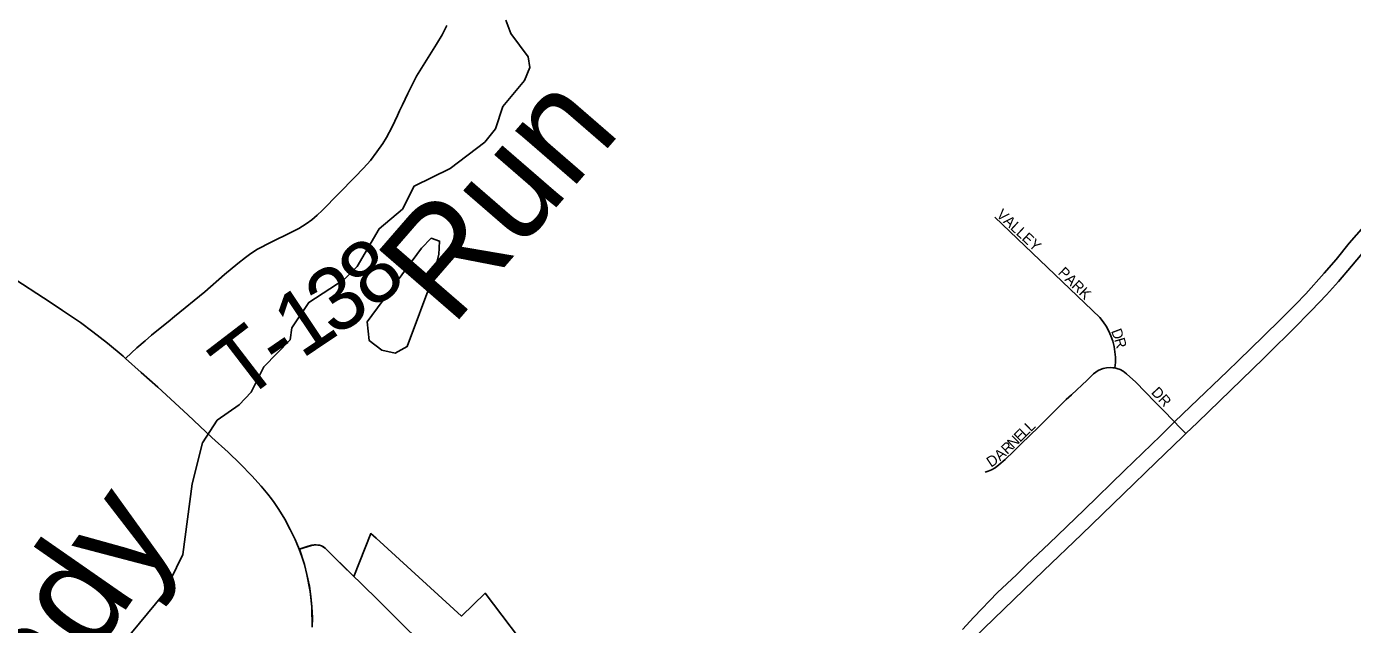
# Model space of a CAD drawing. Extents: x 1410790 to 1770854, y 448063 to 770588.
# Drawn here: x 1542170 to 1548426, y 591709 to 594533 of the extents above; entities that cross this region are included whole.
import ezdxf

# ---------------------------------------------------------------- set-up
doc = ezdxf.new("R2010")
doc.units = 0
for name, color, linetype in [('GM_X_City_Street', 7, 'Continuous'), ('GM_X_Corporation', 7, 'Continuous'), ('GM_X_County_Road', 7, 'Continuous'), ('GM_X_Minor_Lake', 7, 'Continuous'), ('GM_X_Minor_River', 7, 'Continuous'), ('GM_X_Minor_River_Text', 7, 'Continuous'), ('GM_X_State_Route', 7, 'Continuous'), ('GM_X_Township_Road', 7, 'Continuous'), ('GM_X_Township_Road_Text', 7, 'Continuous'), ('GM_X_Township_Subdivision', 7, 'Continuous'), ('GM_X_Township_Subdivision_Text', 7, 'Continuous'), ('GM_X_US_Route', 7, 'Continuous')]:
    doc.layers.add(name, color=color, linetype=linetype)

msp = doc.modelspace()

# ---------------------------------------------------------------- linework, layer by layer
at = {"layer": 'GM_X_City_Street'}
for points in [[(1543742.3, 591908.6), (1543714.4, 591935.8)], [(1544024.3, 591630.1), (1544005.1, 591648.5), (1543957.6, 591695.5), (1543920.8, 591732.4), (1543839.8, 591813.5), (1543742.3, 591908.6)]]:
    msp.add_lwpolyline(points, dxfattribs=at)
at = {"layer": 'GM_X_Corporation'}
msp.add_lwpolyline([(1543518.3, 591696.1), (1543516.7, 591791.8), (1543508.4, 591865.5), (1543493.4, 591944.9), (1543481.4, 591992.8), (1543457.5, 592064.9), (1543515.3, 592082.5), (1543536.5, 592084.9), (1543549.2, 592083.6), (1543561.8, 592080.3), (1543579.7, 592068.8), (1543714.4, 591935.8), (1543794.2, 592138.6), (1543820.6, 592116.3), (1544221.9, 591748.9), (1544334.9, 591856.5), (1544575.1, 591538.1)], dxfattribs=at)
at = {"layer": 'GM_X_County_Road'}
msp.add_lwpolyline([(1543457.4, 592064.9), (1543499.5, 592078.2), (1543516.6, 592082.9), (1543527.6, 592084.6), (1543536.5, 592084.9), (1543544.9, 592084.3), (1543553.3, 592082.9), (1543561.7, 592080.3), (1543570.7, 592075.4), (1543579.8, 592068.8), (1543654.1, 591994), (1543714.4, 591935.8)], dxfattribs=at)
at = {"layer": 'GM_X_Minor_Lake'}
for points in [[(1543776.8, 593138), (1543787.1, 593049.5), (1543846.3, 593004.1), (1543910.2, 592990.7), (1543966.9, 593021.6), (1544087.4, 593346), (1544115.6, 593455.7), (1544118.9, 593519.9), (1544079.1, 593532.7), (1544034.1, 593485.6)], [(1544034.1, 593485.6), (1543776.8, 593138)]]:
    msp.add_lwpolyline(points, dxfattribs=at)
at = {"layer": 'GM_X_Minor_River'}
msp.add_lwpolyline([(1542438.4, 591395.3), (1542816, 591852.6), (1542907.8, 592039.2), (1542952.4, 592373.3), (1543000.3, 592566.8), (1543070.5, 592673.7), (1543174.1, 592745.7), (1543229.4, 592806.7), (1543289.8, 592925.8), (1543414.5, 593053.5), (1543421.6, 593109.5), (1543502.1, 593230.2), (1543668.5, 593338.9), (1543729.8, 593399.8), (1543833.5, 593578.1), (1543943.5, 593670.1), (1543999.7, 593779.2), (1544169.6, 593861.8), (1544332.4, 593986.7), (1544383.7, 594049.8), (1544417.8, 594155.4), (1544520.4, 594277.6), (1544545.6, 594339.2), (1544536.6, 594389.6), (1544454.6, 594499.7), (1544431.8, 594562.3)], dxfattribs=at)
at = {"layer": 'GM_X_State_Route'}
for points in [[(1542088.3, 593357.8), (1542282, 593230.8)], [(1542282, 593230.8), (1542340.7, 593192.3), (1542424.5, 593134.6), (1542482.7, 593091.7), (1542552.3, 593036.9), (1542625.6, 592976.1), (1542637.1, 592965.7), (1542710.9, 592899.5), (1542789.2, 592829.7), (1542931.6, 592698.4), (1543043.8, 592592.7), (1543121.5, 592522), (1543178.2, 592467.3), (1543233.3, 592410.8), (1543278, 592362.5), (1543309.5, 592324.4), (1543326, 592302.7), (1543339.4, 592285), (1543361.4, 592252), (1543388.3, 592206.6), (1543414.8, 592157.3), (1543437.6, 592109.8), (1543445.9, 592091), (1543457.4, 592064.9), (1543469.6, 592030.7), (1543481.4, 591992.8), (1543493.4, 591944.8), (1543504.7, 591890), (1543512.1, 591841), (1543516.7, 591791.8), (1543518.8, 591742.3), (1543518.3, 591696.1)]]:
    msp.add_lwpolyline(points, dxfattribs=at)
at = {"layer": 'GM_X_Township_Road'}
msp.add_lwpolyline([(1542637.1, 592965.7), (1542665.6, 592991.9), (1542690.6, 593014.9), (1542730.7, 593049.2), (1542759.4, 593074.6), (1542792.6, 593101.3), (1542839, 593138), (1542868.5, 593162.7), (1543011.6, 593280.4), (1543105.1, 593361.2), (1543166.7, 593413.8), (1543202.9, 593441.5), (1543228.2, 593461.4), (1543259.6, 593480.8), (1543324.8, 593514), (1543416.9, 593559.7), (1543454.3, 593579.7), (1543490.4, 593601.8), (1543516.8, 593620.6), (1543541.7, 593641.3), (1543565.1, 593663.8), (1543643.5, 593744.5), (1543719.6, 593821.2), (1543760.6, 593864.6), (1543792.6, 593900.2), (1543823.4, 593940.7), (1543851.1, 593981.1), (1543869.2, 594009.5), (1543895.2, 594058.4), (1543919.8, 594112.2), (1543930.4, 594134.9), (1543943.7, 594163.6), (1543969.2, 594216.6), (1544010.5, 594298.6), (1544025.3, 594324.3), (1544104.6, 594450.1), (1544131.2, 594494.1), (1544154, 594538.3)], dxfattribs=at)
at = {"layer": 'GM_X_Township_Subdivision'}
for points in [[(1547305.2, 592920.7), (1547307.5, 592946.2), (1547307.6, 592971.8), (1547305.6, 592997.3), (1547301.4, 593022.5), (1547295.1, 593047.3), (1547286.7, 593071.5), (1547276.3, 593094.9), (1547263.9, 593117.3), (1547249.7, 593138.6), (1547233.7, 593158.6), (1546738.1, 593632.4)], [(1546693.2, 592428.5), (1546707.8, 592432.6), (1546722.9, 592438.8), (1546739.9, 592448.8), (1546758.4, 592462.3), (1546787.9, 592488.4), (1546827.8, 592527.2), (1546863.1, 592561.6), (1546945.6, 592641.5), (1547076, 592771.1), (1547100.2, 592793.1), (1547174, 592863.2), (1547205.1, 592892.6), (1547226.1, 592908), (1547238, 592913.6), (1547250.2, 592918.1), (1547266.3, 592921.4), (1547282.7, 592922.2), (1547295.6, 592921.6), (1547305.2, 592920.7)], [(1547305.2, 592920.7), (1547315.1, 592917.8), (1547330.7, 592912.5), (1547345.1, 592904.9), (1547360.6, 592892.6), (1547404, 592852.6), (1547494.4, 592761), (1547530.5, 592724), (1547587.2, 592665.2)], [(1547587.2, 592665.2), (1547609.2, 592642.5), (1547639.7, 592610.9)]]:
    msp.add_lwpolyline(points, dxfattribs=at)
at = {"layer": 'GM_X_US_Route'}
for points in [[(1548037.9, 592996), (1548143.6, 593100.4), (1548233.2, 593191.6), (1548302.9, 593265.5), (1548359.6, 593329.1), (1548421.4, 593401.3), (1548647.6, 593669.7), (1548988, 594077.4)], [(1546586.8, 591685.9), (1546640.5, 591743.9), (1546752, 591860.4), (1546841, 591944), (1546889.9, 591992.3), (1546994.7, 592091.5), (1547160.1, 592250.9), (1547350.8, 592436.1), (1547520.7, 592600.1), (1547587.2, 592665.2), (1547661.4, 592737.8), (1547836.7, 592905.8), (1547888.3, 592956.2), (1548006.4, 593070.1), (1548088.8, 593150.2), (1548158.2, 593220.2), (1548205.6, 593270.3), (1548293.3, 593368.1), (1548349.5, 593432.4), (1548411.2, 593509), (1548503.2, 593615.8)], [(1546215.1, 591173.7), (1546219.5, 591176.3), (1546222.7, 591178.7), (1546226.2, 591181.9), (1546229.5, 591185.8), (1546232.1, 591189.3), (1546236.2, 591195.5), (1546245.8, 591209.6), (1546295.4, 591278.8), (1546328.1, 591320.1), (1546362.7, 591364.7), (1546408.2, 591414.2), (1546442.1, 591449.4), (1546476, 591483.4), (1546687.5, 591689.5), (1546970.5, 591963.3), (1547147.7, 592133.9), (1547345.6, 592325.8), (1547498.8, 592474.1), (1547623.5, 592595.3), (1547639.7, 592610.9), (1547694.3, 592663.6), (1548008.3, 592966.7), (1548037.9, 592996)]]:
    msp.add_lwpolyline(points, dxfattribs=at)

# ---------------------------------------------------------------- texts
at = {"layer": 'GM_X_Minor_River_Text'}
for s, height, rotation, p in [('Run', 499.94, 49.07088, (1544176, 593109)), ('Glady', 499.93, 55.15136, (1541889.2, 590701.9))]:
    msp.add_text(s, height=height, rotation=rotation, dxfattribs=at).set_placement(p)
at = {"layer": 'GM_X_Township_Road_Text'}
for s, rotation, p in [('8', 40.26741, (1543804, 593188.7)), ('3', 33.96719, (1543622.1, 593063.8)), ('1', 33.8315, (1543468, 592960.4)), ('T', 37.47844, (1543192.4, 592757.1)), ('-', 34.47596, (1543367.1, 592891.2))]:
    msp.add_text(s, height=300, rotation=rotation, dxfattribs=at).set_placement(p)
at = {"layer": 'GM_X_Township_Subdivision_Text'}
for s, rotation, p in [('VALLEY', 317.17636, (1546743, 593639.3)), ('PARK', 315.85301, (1547033.6, 593366.4)), ('D', 290.75816, (1547286.5, 593094.9)), ('R', 286.04549, (1547301.7, 593054.8)), ('DR', 312.88011, (1547473.8, 592802.7)), ('L', 44.17694, (1546882.9, 592592.1)), ('L', 44.1596, (1546908.1, 592616.6)), ('N', 44.171, (1546826.1, 592536.9)), ('E', 44.1596, (1546857.6, 592567.6)), ('D', 33.73856, (1546720.7, 592449.1)), ('A', 42.27644, (1546763.7, 592478.6)), ('R', 44.0141, (1546797.5, 592509.3))]:
    msp.add_text(s, height=50, rotation=rotation, dxfattribs=at).set_placement(p)

doc.saveas('drawing.dxf')
